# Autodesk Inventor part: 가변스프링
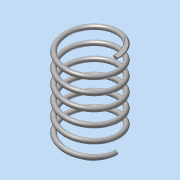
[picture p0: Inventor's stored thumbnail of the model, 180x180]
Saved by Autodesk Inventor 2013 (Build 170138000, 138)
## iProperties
Created: 2018-06
Part Number: 가변스프링
Material: 강철, 연강
Document SubType Name: Modeling
Designer: Administrator
Density: 7.86 g/cm^3
Mass: 82.8068 g
Surface Area: 106.473 cm^2
Volume: 10.5352 cm^3
Author: Administrator
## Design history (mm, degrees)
sketch "스케치1"
  geometry: L1 (0, 0)-(0, 73.25); L2 (0, 0)-(22.5, 0); L3 (0, 73.25)-(22.5, 73.25); C1 r 2 at (22.5, 0)
  constraints: 6 end point, 1 centre point, 1 coincident, 1 parallel, 1 perpendicular, 1 vertical
  dimensions: "d0" = 73.25 distance of L1.start L1.end (derived); "d1" = 22.5 distance of L1.start L2.end; "d2" = 22.5 distance of L1.end L3.end; "d3" = 4 diameter of C1
feature "코일1" sketch "스케치1" pitch "d4" = 10; turns "d6" = 6; dims "d5" = 73.25 (= d0), "d7" = 0, angle "d8" = 90 deg, angle "d9" = 90 deg, "d10" = 0, "d11" = 0
sketch "스케치2"
  geometry: L1 (73.25, 30)-(0, 30); L2 (0, 30)-(0, -30); L3 (0, -30)-(73.25, -30); L4 (73.25, -30)-(73.25, 30); 2 further points
  constraints: 8 end point, 2 parallel, 1 coincident, 1 horizontal, 1 midpoint, 1 perpendicular
  dimensions: "d12" = 60 distance of L3.end L1.start; "d14" = 73.25 distance of L1.start L1.end (derived)
extrude "돌출1" sketch "스케치2" stored distance "d15" = 60; taper "d16" = 0 deg
node "솔리드1"
